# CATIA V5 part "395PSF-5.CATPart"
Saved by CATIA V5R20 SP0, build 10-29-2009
Part number: 395PSF-5
Source: Unknown
Property "ARTICLENO": "395PSF-5"
Property "BOMINFO": "395PSF-5"
Property "CODE": "395PSF-5"
Property "D": "63.000"
Property "D1": "78.000"
Property "H": "8.500"
Property "L": "352.500"
Property "L1": "12.000"
Property "L2": "295.000"
Property "L3": "20.000"
Property "L4": "12.000"
Property "LINA": "395PSF-5"
Property "MAXLOAD": "12000 Kg"
Property "MDW": "24000 Kg"
Property "NB": "395PSF-5"
Property "NBSYN": "$CODE."
Property "NN": "395PSF"
Property "NT": "FIAT Lifting Pins"
Property "SUPPLIER": "CF"
Bounding box of the stored display mesh (mm): x 0 to 352.5, y -40 to 39, z -39 to 39
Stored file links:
  C:\Users\Utente\Desktop\3D files 395PSF\395PSF-5.CATPart
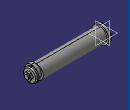
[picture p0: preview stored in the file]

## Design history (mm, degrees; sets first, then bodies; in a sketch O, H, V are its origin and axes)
Body1 "Geometry.1" (main body)
  Solid1 "395PSF-5.catpart": solid without history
